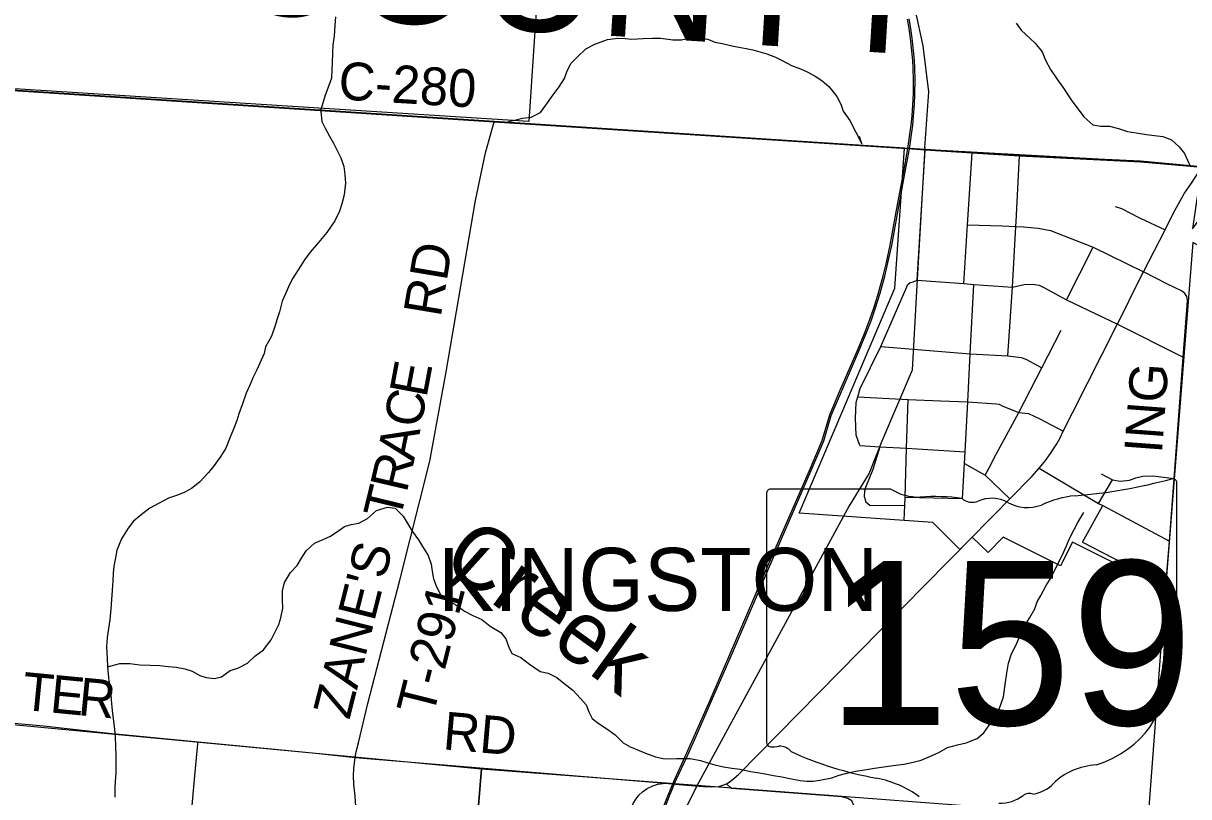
# Model space of a CAD drawing. Extents: x 0 to 42.5, y 0 to 22.
# Drawn here: x 2.796 to 3.672, y 15.433 to 16.014 of the extents above; entities that cross this region are included whole.
import ezdxf

# ---------------------------------------------------------------- set-up
doc = ezdxf.new("R2010")
doc.units = 0
for name, color, linetype in [('GM_X_City_Street', 7, 'Continuous'), ('GM_X_Corporation', 7, 'Continuous'), ('GM_X_Corporation_Text', 7, 'Continuous'), ('GM_X_County_Road', 7, 'Continuous'), ('GM_X_County_Road_Text', 7, 'Continuous'), ('GM_X_County_Text', 7, 'Continuous'), ('GM_X_Interchange_Ramps', 7, 'Continuous'), ('GM_X_Minor_River', 7, 'Continuous'), ('GM_X_Minor_River_Text', 7, 'Continuous'), ('GM_X_Rail_Line', 7, 'Continuous'), ('GM_X_Section', 7, 'Continuous'), ('GM_X_State_Location', 7, 'Continuous'), ('GM_X_State_Route', 7, 'Continuous'), ('GM_X_State_Shield', 7, 'Continuous'), ('GM_X_Township_Road', 7, 'Continuous'), ('GM_X_Township_Road_Text', 7, 'Continuous'), ('SH_Cut_Line', 7, 'Continuous')]:
    doc.layers.add(name, color=color, linetype=linetype)

msp = doc.modelspace()

# ---------------------------------------------------------------- linework, layer by layer
at = {"layer": 'GM_X_City_Street'}
for p, q in [((3.46739, 15.82098), (3.4735, 15.91897)), ((3.5797, 15.8062), (3.59978, 15.84575)), ((3.60572, 15.67543), (3.61437, 15.67088)), ((3.45837, 15.65802), (3.50152, 15.6569)), ((3.59169, 15.62419), (3.60699, 15.65157)), ((3.59169, 15.62419), (3.65438, 15.5918))]:
    msp.add_line(p, q, dxfattribs=at)
for points in [[(3.50252, 15.81838), (3.50539, 15.86259), (3.50889, 15.91669)], [(3.5355, 15.76419), (3.53914, 15.81566), (3.54156, 15.86139), (3.54175, 15.86503), (3.54437, 15.9144)], [(3.61637, 15.87631), (3.62099, 15.87494), (3.63446, 15.86783), (3.65392, 15.85885)], [(3.50539, 15.86259), (3.53138, 15.86185), (3.54156, 15.86139), (3.54734, 15.86113), (3.55834, 15.86014), (3.56762, 15.85823), (3.59978, 15.84575), (3.63746, 15.82729)], [(3.42442, 15.69676), (3.42173, 15.70442), (3.42125, 15.71736), (3.42169, 15.72914), (3.42286, 15.73337), (3.42457, 15.73954), (3.44008, 15.77116), (3.45967, 15.81601)], [(3.45967, 15.81601), (3.46027, 15.81752), (3.46221, 15.81919), (3.46451, 15.81971), (3.46739, 15.82098), (3.50252, 15.81838), (3.51011, 15.81781), (3.53914, 15.81566), (3.54801, 15.81781), (3.55425, 15.81805), (3.55911, 15.81718), (3.56273, 15.81543), (3.5797, 15.8062), (3.61793, 15.78799), (3.66739, 15.76304)], [(3.50152, 15.6569), (3.50297, 15.68312), (3.50346, 15.69201), (3.50554, 15.72947), (3.50741, 15.76554), (3.51011, 15.81781)], [(3.5187, 15.67453), (3.52169, 15.6799), (3.52662, 15.68975), (3.54377, 15.72143), (3.56121, 15.75522), (3.57571, 15.78332)], [(3.44008, 15.77116), (3.50741, 15.76554), (3.5355, 15.76419), (3.54561, 15.76285), (3.5492, 15.76163), (3.56121, 15.75522)], [(3.42286, 15.73337), (3.46071, 15.73136), (3.48493, 15.73034), (3.50554, 15.72947), (3.5268, 15.72806), (3.52908, 15.72783), (3.5319, 15.72624), (3.54377, 15.72143), (3.55107, 15.72075), (3.55955, 15.7167), (3.57726, 15.7074)], [(3.45782, 15.64071), (3.45817, 15.65172), (3.45837, 15.65802), (3.45954, 15.69465), (3.46071, 15.73136)], [(3.42442, 15.69676), (3.43941, 15.69586), (3.45954, 15.69465), (3.50346, 15.69201)], [(3.43941, 15.69586), (3.4343, 15.67867), (3.42869, 15.66529), (3.42787, 15.66245), (3.42778, 15.65846), (3.42884, 15.65445), (3.43201, 15.65191), (3.45817, 15.65172)], [(3.50297, 15.68312), (3.5187, 15.67453), (3.53709, 15.65657)], [(3.55924, 15.67965), (3.60384, 15.65324), (3.60699, 15.65157), (3.65697, 15.62488)], [(3.60384, 15.65324), (3.61437, 15.67088), (3.6201, 15.66988), (3.6271, 15.67061), (3.6317, 15.67241), (3.63686, 15.67363), (3.64447, 15.67385), (3.66065, 15.6719)]]:
    msp.add_lwpolyline(points, dxfattribs=at)
at = {"layer": 'GM_X_Corporation'}
msp.add_lwpolyline([(3.37883, 15.64585), (3.45063, 15.815), (3.45799, 15.92023), (3.63539, 15.91028), (3.68116, 15.90613), (3.67426, 15.85951), (3.68549, 15.87442), (3.68968, 15.86885), (3.7008, 15.89068), (3.70364, 15.90484), (3.72132, 15.90374), (3.70425, 15.84401), (3.67962, 15.84659), (3.67466, 15.84923), (3.65405, 15.58913), (3.58411, 15.62405), (3.57523, 15.60625), (3.53202, 15.62782), (3.52073, 15.61635), (3.50892, 15.62797), (3.49962, 15.61852), (3.47931, 15.63883)], close=True, dxfattribs=at)
at = {"layer": 'GM_X_County_Road'}
for p, q in [((2.52976, 15.98023), (3.14965, 15.93986)), ((3.14965, 15.93986), (3.46338, 15.91963)), ((3.46338, 15.91963), (3.4735, 15.91897)), ((3.4735, 15.91897), (3.50889, 15.91669)), ((3.50889, 15.91669), (3.54437, 15.9144))]:
    msp.add_line(p, q, dxfattribs=at)
for points in [[(3.54437, 15.9144), (3.63549, 15.91001), (3.68127, 15.90587)], [(3.66715, 15.81221), (3.66602, 15.81306), (3.65567, 15.81805), (3.63746, 15.82729)], [(3.65438, 15.5918), (3.65697, 15.62488), (3.66065, 15.6719), (3.66739, 15.76304), (3.67026, 15.80159), (3.67051, 15.80583), (3.67001, 15.8087), (3.66864, 15.81107), (3.66715, 15.81221)], [(3.81125, 14.38966), (3.84476, 14.85241), (3.84714, 14.88263), (3.84662, 14.88758), (3.84418, 14.89065), (3.84154, 14.89333), (3.83908, 14.89469), (3.82959, 14.89592), (3.58977, 14.91333), (3.64105, 15.41464), (3.65438, 15.5918)]]:
    msp.add_lwpolyline(points, dxfattribs=at)
at = {"layer": 'GM_X_Interchange_Ramps'}
for points in [[(2.1, 19.05902), (2.1, 16.00757), (2.52965, 15.98049), (3.14954, 15.94013), (3.47339, 15.91924), (3.50878, 15.91695), (3.54426, 15.91466), (3.63539, 15.91028), (3.68116, 15.90613), (3.70364, 15.90484), (3.72132, 15.90374), (4.44374, 15.85348), (4.57597, 15.84389), (4.70326, 15.83465), (4.83401, 15.82463), (5.0466, 15.8101), (5.21422, 15.79865), (5.23885, 16.11392)], [(4.44374, 15.85348), (3.72132, 15.90374), (3.70364, 15.90484), (3.68116, 15.90613), (3.63539, 15.91028), (3.54426, 15.91466), (3.50878, 15.91695), (3.47339, 15.91924), (3.14954, 15.94013), (2.52965, 15.98049), (2.1, 16.00757), (2.1, 14.1), (5.08492, 14.1)]]:
    msp.add_lwpolyline(points, dxfattribs=at)
at = {"layer": 'GM_X_Minor_River'}
for points in [[(3.01953, 15.94856), (3.02303, 15.96023), (3.02559, 15.96761), (3.02774, 15.9731), (3.02801, 15.97938), (3.02806, 15.98413), (3.02835, 15.99212), (3.0288, 15.99763), (3.02964, 16.00447), (3.0303, 16.01226), (3.03076, 16.01891)], [(3.54178, 16.01412), (3.5457, 16.00893)], [(3.5457, 16.00893), (3.55603, 15.9991), (3.56146, 15.99256), (3.56404, 15.98625), (3.56776, 15.97936), (3.57242, 15.97226), (3.57691, 15.96612), (3.58362, 15.95576), (3.58923, 15.94846), (3.59278, 15.94366), (3.59936, 15.93769), (3.60561, 15.93666), (3.61207, 15.93658), (3.6187, 15.93497), (3.62551, 15.93279), (3.63214, 15.93157), (3.63991, 15.93033), (3.64579, 15.92969), (3.65205, 15.92904), (3.65848, 15.92649), (3.6643, 15.92128), (3.66842, 15.91628), (3.67281, 15.90621)], [(3.1576, 15.93956), (3.17096, 15.9428), (3.17743, 15.94348), (3.1845, 15.94701), (3.18855, 15.95248), (3.19396, 15.96021), (3.19859, 15.96624), (3.20246, 15.97247), (3.20462, 15.97834), (3.20754, 15.98401), (3.21235, 15.9889), (3.21849, 15.99472), (3.22518, 15.99825), (3.22995, 16.00009), (3.23491, 16.00194), (3.24252, 16.00279), (3.24802, 16.00253), (3.25315, 16.00209), (3.2617, 16.00256), (3.26835, 16.00285), (3.27481, 16.00277), (3.28391, 16.00152), (3.29037, 16.00163), (3.29589, 16.00289), (3.30197, 16.00301), (3.30993, 16.00215), (3.3156, 15.9998), (3.32224, 15.99857), (3.32735, 15.99737), (3.3336, 15.99615), (3.3391, 15.99513), (3.34402, 15.99412), (3.35443, 15.99094), (3.36105, 15.98858), (3.36615, 15.98604), (3.37313, 15.98234), (3.37994, 15.97978), (3.38485, 15.97744), (3.39089, 15.97432), (3.39579, 15.97103), (3.40105, 15.9664), (3.40723, 15.95909), (3.4102, 15.95316), (3.41184, 15.948), (3.41689, 15.9409), (3.42597, 15.92341), (3.42415, 15.92882)], [(3.01931, 15.94795), (3.02015, 15.94017), (3.02261, 15.93523), (3.02602, 15.92914), (3.02886, 15.924), (3.03151, 15.91887), (3.03435, 15.91298), (3.03662, 15.90651), (3.03755, 15.90043), (3.03792, 15.89378), (3.03696, 15.88504), (3.03524, 15.87839), (3.03352, 15.87289), (3.0299, 15.86548), (3.024, 15.85675), (3.01772, 15.84935), (3.01144, 15.84195), (3.00706, 15.83626), (3.00402, 15.83152), (2.9983, 15.8226), (2.99583, 15.81766), (2.99354, 15.81253), (2.9903, 15.80532), (2.98839, 15.79715), (2.98667, 15.79203), (2.98495, 15.78614), (2.98228, 15.77892), (2.9779, 15.77076), (2.97675, 15.76582), (2.97351, 15.75861), (2.97141, 15.75367), (2.96855, 15.74798), (2.96607, 15.74209), (2.96341, 15.73602), (2.96054, 15.72804), (2.95768, 15.72064), (2.95634, 15.71551), (2.95425, 15.71019), (2.95139, 15.70298), (2.94795, 15.69481), (2.94434, 15.68874), (2.9392, 15.68172), (2.93501, 15.67641), (2.92835, 15.6692), (2.92227, 15.66446), (2.91675, 15.66143), (2.91086, 15.65916), (2.90497, 15.65727), (2.89091, 15.64969), (2.88577, 15.64552), (2.87874, 15.63983), (2.87474, 15.63452), (2.8696, 15.62655), (2.86617, 15.618), (2.86483, 15.61117), (2.86387, 15.60604), (2.86348, 15.60072), (2.86309, 15.59502), (2.86251, 15.58799), (2.86212, 15.58077), (2.86153, 15.57412), (2.86076, 15.56576), (2.8598, 15.5593), (2.85884, 15.55247), (2.85845, 15.54544), (2.85881, 15.5367), (2.85918, 15.53042), (2.85955, 15.52491), (2.86012, 15.51997), (2.86105, 15.51408), (2.86162, 15.50914), (2.86218, 15.50268), (2.86292, 15.49546), (2.86367, 15.48957), (2.86442, 15.4833), (2.86498, 15.47779), (2.86516, 15.47076), (2.86534, 15.46297), (2.86532, 15.45043), (2.86493, 15.44416), (2.86473, 15.43941), (2.86453, 15.43257)], [(2.85918, 15.53042), (2.86849, 15.53288), (2.8759, 15.53287), (2.8833, 15.53191), (2.89128, 15.5317), (2.8985, 15.53131), (2.90476, 15.53073), (2.91065, 15.53015), (2.9171, 15.529), (2.92261, 15.52709), (2.92849, 15.52385), (2.93323, 15.52232), (2.9395, 15.52174), (2.94482, 15.52287), (2.95128, 15.52761), (2.95698, 15.5295), (2.96439, 15.5331), (2.96972, 15.53841), (2.97637, 15.54315), (2.98208, 15.55074), (2.9878, 15.56213), (2.98933, 15.56725), (2.99086, 15.57447), (2.99068, 15.58093), (2.99069, 15.58758), (2.99222, 15.59385), (2.9966, 15.60125), (3.00174, 15.60656), (3.00479, 15.61207), (3.0084, 15.61757), (3.01468, 15.62326), (3.01981, 15.62553), (3.02627, 15.62837), (3.03122, 15.63159), (3.0373, 15.63576), (3.04224, 15.63727), (3.04794, 15.6384), (3.05459, 15.64181), (3.06125, 15.64788), (3.06961, 15.65034), (3.0753, 15.64976), (3.08118, 15.64367), (3.08421, 15.63853), (3.088, 15.63244), (3.09292, 15.62579), (3.09576, 15.62084), (3.10012, 15.61399), (3.1022, 15.60753), (3.10314, 15.6024), (3.10408, 15.59651), (3.10597, 15.59137), (3.10919, 15.5851), (3.11393, 15.58091), (3.12076, 15.5771), (3.1274, 15.57215), (3.13366, 15.5691), (3.14049, 15.56605), (3.14675, 15.5611), (3.15471, 15.55633), (3.15832, 15.55139), (3.16058, 15.5453), (3.16304, 15.54055), (3.16968, 15.53731), (3.17632, 15.53254), (3.18429, 15.52702), (3.19018, 15.52568), (3.19663, 15.52244), (3.20194, 15.51825), (3.20876, 15.51292), (3.21464, 15.50664), (3.21881, 15.50188), (3.22089, 15.49656), (3.22335, 15.49161), (3.22847, 15.48761), (3.23435, 15.4838), (3.24061, 15.47923), (3.24668, 15.47333), (3.2518, 15.47028), (3.25692, 15.46837), (3.26338, 15.46551), (3.27078, 15.46284), (3.27666, 15.4615), (3.28141, 15.4613), (3.28692, 15.46148), (3.29223, 15.46166), (3.29698, 15.46147), (3.30476, 15.45993), (3.31008, 15.45821), (3.31539, 15.45687), (3.32185, 15.45515), (3.32811, 15.45419), (3.33457, 15.45342), (3.34235, 15.45189), (3.34748, 15.45112), (3.35317, 15.44997), (3.35944, 15.44882), (3.3657, 15.44786), (3.37178, 15.44651), (3.37956, 15.44498), (3.3845, 15.4444), (3.38943, 15.44439)], [(3.38943, 15.44439), (3.39437, 15.44515), (3.4033, 15.44703), (3.409, 15.44892), (3.4147, 15.45043), (3.42116, 15.45194), (3.428, 15.45307), (3.43541, 15.45438), (3.44946, 15.45626), (3.45744, 15.45739), (3.46447, 15.4587), (3.47055, 15.4604), (3.47758, 15.46324), (3.48366, 15.46608), (3.49031, 15.46987), (3.49772, 15.47175), (3.50437, 15.47326), (3.51254, 15.47648), (3.51768, 15.48084), (3.52281, 15.48824), (3.52795, 15.49545), (3.53024, 15.5021), (3.53234, 15.50798), (3.53369, 15.5171), (3.53484, 15.52565), (3.53618, 15.53306), (3.53828, 15.54008), (3.54152, 15.54654), (3.54381, 15.55166), (3.54724, 15.55945), (3.55219, 15.56761), (3.55581, 15.57406), (3.55772, 15.57919), (3.56039, 15.58394), (3.56477, 15.5921), (3.568, 15.59703), (3.57048, 15.60235), (3.57639, 15.61412), (3.57944, 15.62095), (3.5823, 15.62741), (3.58554, 15.63367), (3.58858, 15.63936), (3.59277, 15.64639)]]:
    msp.add_lwpolyline(points, dxfattribs=at)
at = {"layer": 'GM_X_Rail_Line'}
for points in [[(3.46046, 15.91995), (3.46297, 15.93762), (3.46365, 15.94439), (3.46433, 15.95281), (3.46464, 15.96118), (3.46471, 15.97163), (3.46447, 15.98001), (3.46416, 15.98613), (3.46358, 15.99338), (3.46252, 16.0027), (3.46153, 16.01002), (3.4603, 16.01713)], [(3.46165, 15.91978), (3.46416, 15.93748), (3.46485, 15.94428), (3.46553, 15.95274), (3.46584, 15.96116), (3.46591, 15.97164), (3.46567, 15.98006), (3.46536, 15.98621), (3.46478, 15.9935), (3.46371, 16.00284), (3.46271, 16.0102), (3.46148, 16.01735)], [(3.47328, 15.92052), (3.4762, 15.96254), (3.47191, 15.99718), (3.46621, 16.02373)], [(3.47328, 15.92052), (3.46744, 15.82178), (3.46367, 15.75338), (3.44096, 15.69989), (3.43137, 15.67586), (3.41647, 15.65133), (3.3017, 15.44053), (3.22062, 15.27562), (3.19329, 15.2099), (3.17616, 15.16485), (3.16703, 15.1369), (3.161, 15.10576), (3.15922, 15.07853), (3.15956, 15.04953), (3.15856, 14.90389), (3.14925, 14.82993)], [(3.27265, 15.41458), (3.28083, 15.4352), (3.28538, 15.44609), (3.29322, 15.46295), (3.3003, 15.47874), (3.31184, 15.50527), (3.32827, 15.54314), (3.3539, 15.60273), (3.38724, 15.67978), (3.39622, 15.70054), (3.40185, 15.71972), (3.40875, 15.73594), (3.42312, 15.76927), (3.42792, 15.78079), (3.43169, 15.79093), (3.43491, 15.79991), (3.43854, 15.81155), (3.44203, 15.82415), (3.44436, 15.83415), (3.44717, 15.84736), (3.45195, 15.8737), (3.4571, 15.90147), (3.46047, 15.91999)], [(3.27376, 15.41413), (3.28194, 15.43475), (3.28648, 15.44561), (3.29431, 15.46245), (3.30139, 15.47826), (3.31294, 15.50479), (3.32937, 15.54267), (3.35501, 15.60226), (3.38834, 15.67931), (3.39735, 15.70014), (3.40298, 15.71931), (3.40986, 15.73547), (3.42422, 15.7688), (3.42903, 15.78035), (3.43282, 15.79052), (3.43605, 15.79953), (3.43969, 15.81121), (3.44319, 15.82386), (3.44553, 15.83389), (3.44835, 15.84713), (3.45313, 15.87349), (3.45828, 15.90125), (3.46165, 15.91978)]]:
    msp.add_lwpolyline(points, dxfattribs=at)
at = {"layer": 'GM_X_Section'}
for points in [[(2.69081, 16.48651), (3.2094, 16.44994), (3.17574, 15.9403), (2.65903, 15.97303)], [(2.62095, 15.50275), (3.14004, 15.45367), (3.09918, 14.95159), (2.58723, 14.98757)], [(3.14004, 15.45367), (3.64215, 15.41565), (3.61158, 15.16447), (3.59088, 14.91475), (3.09918, 14.95159)]]:
    msp.add_lwpolyline(points, close=True, dxfattribs=at)
at = {"layer": 'GM_X_State_Route'}
for p, q in [((3.50462, 15.62362), (3.52535, 15.64465)), ((3.49772, 15.61661), (3.50462, 15.62362)), ((3.49081, 15.60961), (3.49772, 15.61661))]:
    msp.add_line(p, q, dxfattribs=at)
for points in [[(3.63526, 15.82287), (3.63746, 15.82729), (3.65392, 15.85885), (3.65954, 15.87058), (3.66228, 15.87569), (3.66502, 15.88068), (3.66839, 15.88642), (3.67351, 15.8939), (3.68127, 15.90587)], [(3.61771, 15.78755), (3.61793, 15.78799), (3.63526, 15.82287)], [(3.55953, 15.68001), (3.56392, 15.68545), (3.56772, 15.69069), (3.56997, 15.69418), (3.5724, 15.69805), (3.57483, 15.7026), (3.57726, 15.7074), (3.58419, 15.72137), (3.61771, 15.78755)], [(3.52535, 15.64465), (3.53709, 15.65657), (3.55369, 15.67354), (3.55924, 15.67965), (3.55953, 15.68001)], [(3.32826, 15.44522), (3.33328, 15.44963), (3.37808, 15.49508), (3.44003, 15.55809), (3.49081, 15.60961)], [(3.22092, 15.33472), (3.22599, 15.33968), (3.23429, 15.35011), (3.23748, 15.35522), (3.23929, 15.35873), (3.24132, 15.3631), (3.24291, 15.36821), (3.2443, 15.37406), (3.24589, 15.38289), (3.24749, 15.39418), (3.251, 15.41738), (3.25217, 15.42291), (3.25409, 15.4277), (3.25632, 15.43121), (3.25835, 15.43409), (3.26111, 15.43643), (3.26452, 15.43898), (3.26899, 15.4409), (3.27261, 15.44218), (3.27814, 15.44292), (3.28841, 15.44205)], [(3.28841, 15.44205), (3.30688, 15.44048), (3.31294, 15.44016), (3.31837, 15.44058), (3.32157, 15.44154), (3.32433, 15.4425), (3.3271, 15.4442), (3.32826, 15.44522)]]:
    msp.add_lwpolyline(points, dxfattribs=at)
at = {"layer": 'GM_X_State_Shield'}
for p, q in [((3.66261, 15.57069), (3.66261, 15.66859)), ((3.35438, 15.66073), (3.35438, 15.47357)), ((3.44768, 15.66395), (3.35741, 15.66395)), ((3.66258, 15.57071), (3.66261, 15.57069))]:
    msp.add_line(p, q, dxfattribs=at)
for centre, major_axis, start_param, end_param in [((3.55281, 15.91911), (0.32688, 0), 4.814394, 5.042369), ((3.65919, 15.669), (0.00343, 0), 6.141152, 7.989035), ((3.35791, 15.66113), (0.00357, 0), 1.712693, 3.28349), ((3.46918, 15.68568), (0.03464, 0), 4.042523, 4.731795), ((3.48066, 15.55888), (0.12434, 0), 1.404758, 1.657858), ((3.50889, 15.6621), (0.00999, 0), 3.836095, 5.185415), ((3.52356, 15.64047), (0.02077, 0), 0.950623, 2.079405), ((3.59451, 15.60679), (0.06576, 0), 1.699011, 2.107814), ((3.55037, 15.67014), (0.02499, 0), 4.081561, 5.145723), ((3.65895, 15.57031), (0.00367, 0), 5.05454, 6.418171), ((3.66182, 15.5635), (0.00531, 0), 1.883978, 3.671073), ((3.62803, 15.55112), (0.03188, 0), 5.934695, 6.695948), ((3.67491, 15.52971), (0.02319, 0), 2.387724, 3.262537), ((3.57112, 15.51726), (0.08176, 0), 5.101752, 6.440018), ((3.35794, 15.47316), (0.0036, 0), 3.00124, 4.508301), ((3.35848, 15.49231), (0.02749, 0), 4.665946, 4.897461), ((3.36411, 15.46278), (0.00991, 0), 0.519207, 1.627899), ((3.48927, 15.63093), (0.23605, 0), 4.195997, 4.488961), ((3.6056, 15.42103), (0.04478, 0), 1.647645, 2.488434), ((3.41889, 15.38949), (0.07386, 0), 0.823519, 1.323587), ((3.54886, 15.45543), (0.02641, 0), 4.937069, 5.64225), ((3.52927, 15.44783), (0.02497, 0), 4.691044, 5.507374), ((3.55186, 15.42971), (0.00703, 0), 1.147584, 2.315152)]:
    msp.add_ellipse(centre, major_axis=major_axis, ratio=0.8, start_param=start_param, end_param=end_param, dxfattribs=at)
at = {"layer": 'GM_X_Township_Road'}
for points in [[(3.04511, 15.46217), (3.04604, 15.46656), (3.0478, 15.47326), (3.05484, 15.50278), (3.07888, 15.59546), (3.10133, 15.68494), (3.1136, 15.752), (3.13556, 15.88085), (3.14317, 15.91663), (3.14965, 15.93986)], [(2.61806, 15.50076), (2.65724, 15.50013), (2.81108, 15.48603), (2.86011, 15.48048), (2.88866, 15.4777), (2.9272, 15.47405), (2.98739, 15.46829), (3.0157, 15.46545), (3.04511, 15.46217), (3.27814, 15.44292)], [(2.92068, 15.40401), (2.92461, 15.44576), (2.92677, 15.46995), (2.9272, 15.47405)], [(3.03382, 15.35787), (3.03419, 15.3617), (3.03566, 15.37713), (3.03609, 15.3803), (3.03674, 15.38323), (3.03886, 15.39067), (3.04303, 15.40399), (3.04476, 15.41154), (3.04547, 15.4177), (3.04567, 15.42544), (3.04511, 15.43316), (3.04413, 15.44234), (3.04394, 15.44859), (3.04413, 15.45393), (3.04511, 15.46217)], [(3.1718, 14.94504), (3.21901, 15.01819), (3.24494, 15.0572), (3.27596, 15.12191), (3.2912, 15.16034), (3.30581, 15.19368), (3.31914, 15.22035), (3.33121, 15.24544), (3.35217, 15.28418), (3.38369, 15.34846), (3.41969, 15.42143), (3.42005, 15.42565), (3.4184, 15.42968), (3.41547, 15.43151), (3.41089, 15.43261), (3.32808, 15.43902), (3.32433, 15.4425)]]:
    msp.add_lwpolyline(points, dxfattribs=at)
at = {"layer": 'SH_Cut_Line'}
for points in [[(2.1, 20.9), (2.1, 16.00757), (2.52965, 15.98049), (3.14954, 15.94013), (3.47339, 15.91924), (3.50878, 15.91695), (3.54426, 15.91466), (3.63539, 15.91028), (3.68116, 15.90613), (3.70364, 15.90484), (3.72132, 15.90374), (4.44374, 15.85348)], [(4.44374, 15.85348), (3.72132, 15.90374), (3.70364, 15.90484), (3.68116, 15.90613), (3.63539, 15.91028), (3.54426, 15.91466), (3.50878, 15.91695), (3.47339, 15.91924), (3.14954, 15.94013), (2.52965, 15.98049), (2.1, 16.00757), (2.1, 14.1), (8.06989, 14.1)]]:
    msp.add_lwpolyline(points, dxfattribs=at)

# ---------------------------------------------------------------- texts
at = {"layer": 'GM_X_Corporation_Text'}
msp.add_text('KINGSTON', height=0.047348, rotation=0.00001, dxfattribs=at).set_placement((3.10749, 15.57243))
at = {"layer": 'GM_X_County_Road_Text'}
for s, rotation, p in [('C-280', 356.43869, (3.03209, 15.95695)), ('ING', 85.74869, (3.65136, 15.69029))]:
    msp.add_text(s, height=0.028409, rotation=rotation, dxfattribs=at).set_placement(p)
at = {"layer": 'GM_X_County_Text'}
msp.add_text('PICKAWAY COUNTY', height=0.094697, rotation=356.44596, dxfattribs=at).set_placement((2.24398, 16.06627))
at = {"layer": 'GM_X_Minor_River_Text'}
msp.add_text('Creek', height=0.047347, rotation=323.9998, dxfattribs=at).set_placement((3.10847, 15.60668))
at = {"layer": 'GM_X_State_Location'}
for s, p in [('r', (3.48302, 15.58982)), ('s', (3.48303, 15.58982))]:
    msp.add_text(s, height=0.0000947, dxfattribs=at).set_placement(p)
msp.add_text('159', height=0.0000947, rotation=0.00001, dxfattribs=at).set_placement((3.4496, 15.58293))
at = {"layer": 'GM_X_State_Shield'}
msp.add_text('159', height=0.123297, dxfattribs=at).set_placement((3.39971, 15.48677))
at = {"layer": 'GM_X_Township_Road_Text'}
for s, height, rotation, p in [('RD', 0.028409, 80.53705, (3.10941, 15.79254)), ('E', 0.02841, 79.39742, (3.09872, 15.73203)), ('C', 0.02841, 79.37707, (3.09441, 15.70908)), ('A', 0.02841, 78.45056, (3.08931, 15.6841)), ('R', 0.02841, 76.87193, (3.08383, 15.66054)), ('T', 0.02841, 76.31923, (3.07873, 15.6396)), ("ZANE'S", 0.028409, 75.81534, (3.04083, 15.49008)), ('T-291', 0.028409, 75.82773, (3.10366, 15.49238)), ('T', 0.02841, 354.48429, (2.79408, 15.4983)), ('E', 0.02841, 354.48994, (2.81524, 15.49625)), ('R', 0.02841, 354.48825, (2.83639, 15.49421)), ('RD', 0.028409, 355.07376, (3.11056, 15.4685))]:
    msp.add_text(s, height=height, rotation=rotation, dxfattribs=at).set_placement(p)

doc.saveas('drawing.dxf')
